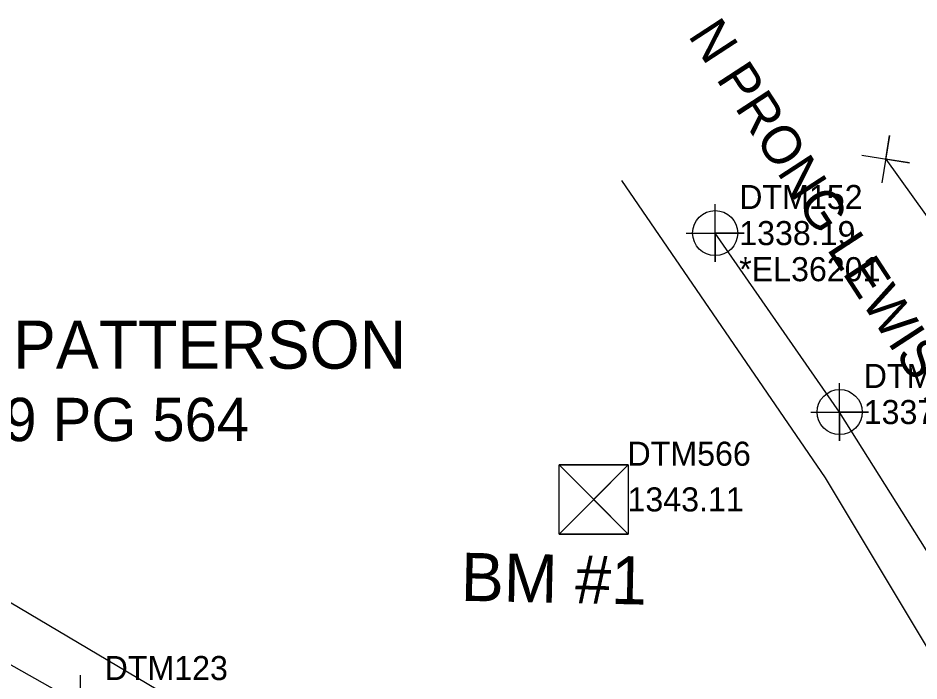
# Model space of a CAD drawing. Extents: x 1303760 to 1305114, y 904598 to 905144.
# Drawn here: x 1304141.1 to 1304234.8, y 904886.6 to 904955.5 of the extents above; entities that cross this region are included whole.
import ezdxf

# ---------------------------------------------------------------- set-up
doc = ezdxf.new("R2010")
doc.units = 0
for name, color, linetype in [('CTL Bench Mark CELL', 7, 'Continuous'), ('CTL Bench Mark Cogo Elevation', 7, 'Continuous'), ('CTL Bench Mark Cogo Number', 7, 'Continuous'), ('CTL Bench Mark Text', 7, 'Continuous'), ('Exist Hydro Jurisdictional Stream or Body of Water', 7, 'Continuous'), ('Exist Hydro Jurisdictional Stream or Body of Water Text', 7, 'Continuous'), ('Exist Hydro Stream or Body of Water Cogo Comment', 7, 'Continuous'), ('Exist Hydro Stream or Body of Water Cogo Elevation', 7, 'Continuous'), ('Exist Hydro Stream or Body of Water Cogo Number', 7, 'Continuous'), ('Exist Hydro Stream or Body of Water Cogo Point CELL', 7, 'Continuous'), ('Exist Property Corner CELL', 7, 'Continuous'), ('Exist Property Deed Book Text', 7, 'Continuous'), ('Exist Property Line', 7, 'Continuous'), ('Exist Property Owner Text', 7, 'Continuous'), ('Exist Vegetation Woods Line', 7, 'Continuous')]:
    doc.layers.add(name, color=color, linetype=linetype)

msp = doc.modelspace()

# ---------------------------------------------------------------- linework, layer by layer
at = {"layer": 'CTL Bench Mark CELL'}
msp.add_line((1304200.979, 904905.448), (1304200.979, 904905.448), dxfattribs=at)
msp.add_lwpolyline([(1304197.379, 904909.035), (1304204.567, 904909.035), (1304204.567, 904901.848), (1304197.379, 904901.848)], close=True, dxfattribs=at)
for points in [[(1304204.567, 904909.035), (1304197.379, 904901.848), (1304200.973, 904905.442), (1304204.567, 904901.848), (1304197.379, 904909.035)], [(1304200.973, 904905.442), (1304204.567, 904909.035), (1304197.379, 904909.035), (1304200.973, 904905.442)], [(1304200.973, 904905.442), (1304197.379, 904901.848), (1304204.567, 904901.848), (1304200.973, 904905.442)]]:
    msp.add_lwpolyline(points, dxfattribs=at)
at = {"layer": 'Exist Hydro Jurisdictional Stream or Body of Water'}
msp.add_lwpolyline([(1304086.737, 904920.467), (1304117.246, 904901.303), (1304147.629, 904884.176), (1304181.384, 904867.439), (1304200.772, 904859.571), (1304219.149, 904855.326), (1304237.904, 904861.515), (1304264.914, 904869.609), (1304261.855, 904877.782), (1304240.828, 904891.776), (1304226.533, 904914.525), (1304213.592, 904933.12)], dxfattribs=at)
at = {"layer": 'Exist Hydro Stream or Body of Water Cogo Point CELL'}
for points in [[(1304210.592, 904933.12), (1304216.592, 904933.12), (1304213.592, 904933.12), (1304213.592, 904930.12), (1304213.592, 904936.12)], [(1304223.533, 904914.525), (1304229.533, 904914.525), (1304226.533, 904914.525), (1304226.533, 904911.525), (1304226.533, 904917.525)], [(1304144.629, 904884.176), (1304150.629, 904884.176), (1304147.629, 904884.176), (1304147.629, 904881.176), (1304147.629, 904887.176)]]:
    msp.add_lwpolyline(points, dxfattribs=at)
for centre in [(1304213.592, 904933.12), (1304226.533, 904914.525)]:
    msp.add_circle(centre, 2.344, dxfattribs=at)
at = {"layer": 'Exist Property Corner CELL'}
msp.add_line((1304231.317, 904940.811), (1304231.317, 904940.811), dxfattribs=at)
msp.add_lwpolyline([(1304228.851, 904941.218), (1304233.784, 904940.405), (1304231.317, 904940.811), (1304231.724, 904943.278), (1304230.911, 904938.344)], dxfattribs=at)
at = {"layer": 'Exist Property Line'}
msp.add_line((1304231.317, 904940.811), (1304245.293, 904921.32), dxfattribs=at)
at = {"layer": 'Exist Vegetation Woods Line'}
msp.add_lwpolyline([(1304203.856, 904938.589), (1304225.022, 904907.703), (1304240.09, 904882.563), (1304259.104, 904871.429), (1304258.745, 904873.584), (1304256.234, 904870.711), (1304261.615, 904869.993), (1304226.099, 904864.605), (1304211.748, 904861.014), (1304180.178, 904871.07), (1304086.902, 904926.378)], dxfattribs=at)

# ---------------------------------------------------------------- texts
at = {"layer": 'CTL Bench Mark Cogo Elevation'}
msp.add_text('1343.11', height=2.5, dxfattribs=at).set_placement((1304204.479, 904904.198))
at = {"layer": 'CTL Bench Mark Cogo Number'}
msp.add_text('DTM566', height=2.5, dxfattribs=at).set_placement((1304204.479, 904908.948))
at = {"layer": 'CTL Bench Mark Text'}
msp.add_text('BM #1', height=5, rotation=358.80522, dxfattribs=at).set_placement((1304187.127, 904894.915))
at = {"layer": 'Exist Hydro Jurisdictional Stream or Body of Water Text'}
msp.add_text('N PRONG LEWIS FORK CREEK', height=4, rotation=303.06404, dxfattribs=at).set_placement((1304210.704, 904953.654))
at = {"layer": 'Exist Hydro Stream or Body of Water Cogo Comment'}
msp.add_text('*EL36201', height=2.5, dxfattribs=at).set_placement((1304216.092, 904928.12))
at = {"layer": 'Exist Hydro Stream or Body of Water Cogo Elevation'}
for s, p in [('1338.19', (1304216.092, 904931.87)), ('1337.76', (1304229.033, 904913.275))]:
    msp.add_text(s, height=2.5, dxfattribs=at).set_placement(p)
at = {"layer": 'Exist Hydro Stream or Body of Water Cogo Number'}
for s, p in [('DTM152', (1304216.092, 904935.62)), ('DTM151', (1304229.033, 904917.025)), ('DTM123', (1304150.129, 904886.676))]:
    msp.add_text(s, height=2.5, dxfattribs=at).set_placement(p)
at = {"layer": 'Exist Property Deed Book Text'}
msp.add_text('DB 519 PG 564', height=4.5, dxfattribs=at).set_placement((1304122.99, 904911.504))
at = {"layer": 'Exist Property Owner Text'}
msp.add_text('LOUIS M. PATTERSON', height=5, dxfattribs=at).set_placement((1304109.397, 904919.029))

doc.saveas('drawing.dxf')
